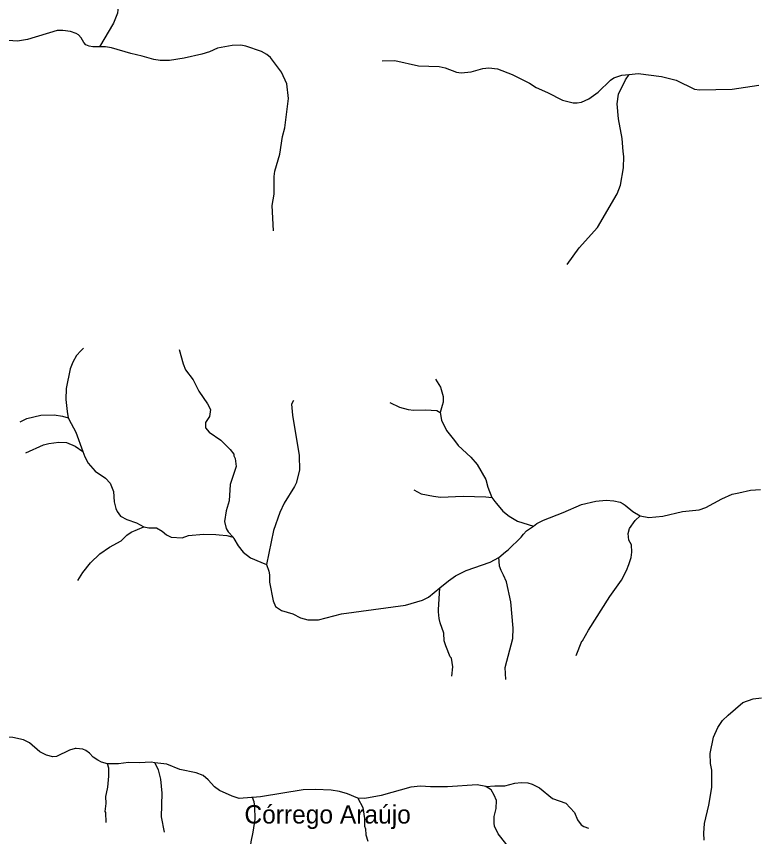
# Model space of a CAD drawing. Extents: x 396 to 422.2, y 7649.8 to 7677.6.
# Drawn here: x 418.881 to 422.13, y 7659.698 to 7663.274 of the extents above; entities that cross this region are included whole.
import ezdxf
from ezdxf.enums import TextEntityAlignment as Align

# ---------------------------------------------------------------- set-up
doc = ezdxf.new("R2010")
doc.units = 0
doc.header["$LTSCALE"] = 0.032
doc.layers.add('61', color=7, linetype='Continuous')
doc.layers.add('7', color=7, linetype='Continuous', lineweight=25)

msp = doc.modelspace()

# ---------------------------------------------------------------- linework, layer by layer
at = {"layer": '7'}
for points in [[(419.1658, 7663.6844), (419.1843, 7663.6415), (419.207, 7663.5626), (419.2258, 7663.5203), (419.2495, 7663.4776), (419.2741, 7663.4332), (419.309, 7663.3852), (419.3109, 7663.3808), (419.3181, 7663.3633), (419.3247, 7663.3476), (419.3247, 7663.3169), (419.3209, 7663.2878), (419.3047, 7663.244), (419.2429, 7663.1414)], [(419.2429, 7663.1414), (419.2223, 7663.1414), (419.2182, 7663.1414), (419.2135, 7663.1414), (419.1976, 7663.1438), (419.1839, 7663.1501), (419.1744, 7663.1594), (419.1626, 7663.1808), (419.1509, 7663.1941), (419.1416, 7663.1999), (419.1166, 7663.2075), (419.0825, 7663.2125), (419.0584, 7663.2124), (418.9289, 7663.1725), (418.8861, 7663.1662), (418.8265, 7663.1695), (418.6753, 7663.1853), (418.6446, 7663.1853), (418.6035, 7663.1807), (418.5732, 7663.1724), (418.5063, 7663.1394), (418.4717, 7663.1276), (418.4202, 7663.1209), (418.3705, 7663.1225)], [(420.0016, 7662.3393), (419.9963, 7662.4491), (420.0042, 7662.4995), (420.005, 7662.5757), (420.0076, 7662.5991), (420.0296, 7662.6726), (420.041, 7662.7503), (420.0504, 7662.7875), (420.0664, 7662.9155), (420.0601, 7662.9793), (420.0365, 7663.0313), (419.9884, 7663.0943), (419.9726, 7663.1077), (419.9487, 7663.1214), (419.8811, 7663.1447), (419.8591, 7663.1486), (419.8217, 7663.147), (419.7574, 7663.1348), (419.7229, 7663.1197), (419.6888, 7663.1088), (419.6119, 7663.0912), (419.5481, 7663.0816), (419.5079, 7663.0818), (419.4801, 7663.0858), (419.4297, 7663.1009), (419.3802, 7663.1116), (419.2951, 7663.1373), (419.2692, 7663.1414), (419.2429, 7663.1414)], [(420.4757, 7663.0807), (420.5311, 7663.0814), (420.6346, 7663.0585), (420.7243, 7663.056), (420.7498, 7663.0495), (420.7994, 7663.0308), (420.82, 7663.0285), (420.8643, 7663.0323), (420.9143, 7663.0464), (420.9402, 7663.0497), (420.9785, 7663.045), (421.0423, 7663.0212), (421.1185, 7662.9823), (421.1477, 7662.9644), (421.197, 7662.9423), (421.2614, 7662.9085), (421.308, 7662.8976), (421.3256, 7662.8967), (421.3444, 7662.8999), (421.3762, 7662.9139), (421.4172, 7662.9428), (421.4706, 7662.9961), (421.4859, 7663.0054), (421.5212, 7663.0178), (421.5531, 7663.0207)], [(421.2818, 7662.1927), (421.3344, 7662.2656), (421.4152, 7662.3538), (421.4997, 7662.4998), (421.5147, 7662.5377), (421.5274, 7662.6143), (421.5298, 7662.6626), (421.5259, 7662.6853), (421.5226, 7662.7419), (421.5068, 7662.8277), (421.5004, 7662.8925), (421.5068, 7662.9354), (421.5372, 7662.9968), (421.5531, 7663.0207)], [(421.5531, 7663.0207), (421.5924, 7663.0242), (421.694, 7663.0113), (421.7571, 7662.9955), (421.837, 7662.9573), (421.8589, 7662.9541), (422.0024, 7662.9572), (422.1175, 7662.9743)], [(419.1731, 7661.8275), (419.1621, 7661.8159), (419.143, 7661.796), (419.1261, 7661.7671), (419.1155, 7661.7374), (419.0975, 7661.6522), (419.0961, 7661.6044), (419.1021, 7661.5511), (419.1061, 7661.5244)], [(419.5906, 7661.8218), (419.6075, 7661.7598), (419.6181, 7661.7326), (419.6508, 7661.6898), (419.6758, 7661.6396), (419.7133, 7661.5849), (419.7264, 7661.5606), (419.7233, 7661.5304), (419.7045, 7661.503), (419.7046, 7661.4802), (419.7218, 7661.4607), (419.7724, 7661.4266), (419.8134, 7661.3865), (419.8287, 7661.3653), (419.8289, 7661.3586), (419.8351, 7661.3467), (419.8383, 7661.3121), (419.8129, 7661.2334), (419.8088, 7661.1617), (419.7954, 7661.1186), (419.7874, 7661.0727), (419.7956, 7661.0412), (419.8041, 7661.0273), (419.8256, 7661.0035)], [(420.7087, 7661.6929), (420.7292, 7661.6578), (420.739, 7661.6265), (420.7411, 7661.6171), (420.742, 7661.6035), (420.7411, 7661.5915), (420.7372, 7661.5772), (420.7291, 7661.5476)], [(420.0882, 7661.5988), (420.0804, 7661.5829), (420.0842, 7661.5356), (420.1136, 7661.3603), (420.1158, 7661.2961), (420.1006, 7661.2391), (420.0936, 7661.2239), (420.0486, 7661.1526), (420.03, 7661.1109), (420.0013, 7661.0329), (419.9711, 7660.8849)], [(420.5088, 7661.5907), (420.5507, 7661.5702), (420.5896, 7661.56), (420.6132, 7661.5569), (420.664, 7661.5593), (420.7141, 7661.5554), (420.7291, 7661.5476)], [(418.8974, 7661.5067), (418.9257, 7661.5204), (418.9875, 7661.5361), (419.0447, 7661.5369), (419.082, 7661.5314), (419.1061, 7661.5244)], [(420.7291, 7661.5476), (420.7346, 7661.514), (420.7564, 7661.4689), (420.7905, 7661.4245), (420.8065, 7661.4037), (420.8626, 7661.3517), (420.8892, 7661.3211), (420.9282, 7661.2545), (420.936, 7661.2212), (420.9541, 7661.1767)], [(419.1061, 7661.5244), (419.1187, 7661.4996), (419.1396, 7661.4614), (419.1704, 7661.3776)], [(418.9219, 7661.3709), (418.9991, 7661.406), (419.0221, 7661.4118), (419.0657, 7661.4172), (419.0992, 7661.4165), (419.1375, 7661.4001), (419.1704, 7661.3776)], [(419.1704, 7661.3776), (419.1793, 7661.3534), (419.1933, 7661.3258), (419.2245, 7661.2909), (419.2692, 7661.2607), (419.2895, 7661.2397), (419.3041, 7661.2024), (419.3073, 7661.1578), (419.3139, 7661.1287), (419.3199, 7661.1153), (419.3347, 7661.095), (419.3618, 7661.0814), (419.4045, 7661.0663), (419.4365, 7661.049), (419.4366, 7661.049)], [(420.6134, 7661.2107), (420.646, 7661.1924), (420.6989, 7661.1829), (420.7295, 7661.1774), (420.8285, 7661.182), (420.9281, 7661.1788), (420.9541, 7661.1767)], [(421.6004, 7661.0969), (421.6382, 7661.0891), (421.6997, 7661.0959), (421.7858, 7661.115), (421.8584, 7661.1232), (421.8876, 7661.1324), (421.9574, 7661.1705), (422.0024, 7661.1907), (422.0309, 7661.197), (422.0818, 7661.2082), (422.1258, 7661.2121)], [(420.9541, 7661.1767), (420.9672, 7661.1588), (420.9735, 7661.1501), (421.0017, 7661.1169), (421.0292, 7661.095), (421.0662, 7661.0737), (421.1349, 7661.0523)], [(421.1349, 7661.0523), (421.1498, 7661.0627), (421.1797, 7661.0783), (421.265, 7661.1113), (421.3444, 7661.1466), (421.407, 7661.1606), (421.4527, 7661.1644), (421.4851, 7661.1627), (421.5128, 7661.1566), (421.5268, 7661.1497), (421.5354, 7661.1429), (421.5693, 7661.116), (421.6004, 7661.0969)], [(421.3219, 7660.4879), (421.3455, 7660.5505), (421.3493, 7660.5521), (421.3748, 7660.5989), (421.4688, 7660.7444), (421.5195, 7660.8163), (421.5417, 7660.858), (421.551, 7660.8852), (421.561, 7660.9144), (421.5641, 7660.9384), (421.5626, 7660.9701), (421.5515, 7660.991), (421.5483, 7661.0198), (421.5546, 7661.0416), (421.5787, 7661.0759), (421.6004, 7661.0969)], [(419.1489, 7660.815), (419.1698, 7660.8498), (419.2033, 7660.8915), (419.245, 7660.9309), (419.2865, 7660.9603), (419.3378, 7660.9877), (419.3624, 7661.012), (419.3809, 7661.0259), (419.4366, 7661.049)], [(419.4366, 7661.049), (419.4574, 7661.0439), (419.4917, 7661.0439), (419.5157, 7661.0298), (419.5353, 7661.0141), (419.5561, 7661.0034), (419.6031, 7661.0003), (419.6313, 7661.0114), (419.6963, 7661.0162), (419.7507, 7661.0148), (419.7641, 7661.0145), (419.7985, 7661.0105), (419.8256, 7661.0035)], [(420.9841, 7660.9147), (421.0134, 7660.9393), (421.025, 7660.9484), (421.0822, 7661.0039), (421.0925, 7661.0165), (421.1046, 7661.0311), (421.1349, 7661.0523)], [(419.8256, 7661.0035), (419.8294, 7660.9972), (419.8483, 7660.9654), (419.87, 7660.9376), (419.9011, 7660.9133), (419.9465, 7660.8943), (419.9711, 7660.8849)], [(419.9711, 7660.8849), (419.9819, 7660.8552), (419.9843, 7660.8395), (419.9836, 7660.8069), (419.9996, 7660.7267), (420.0107, 7660.7014), (420.0363, 7660.6847), (420.0865, 7660.6695), (420.1188, 7660.6518), (420.1507, 7660.643), (420.1976, 7660.6438), (420.2977, 7660.67), (420.577, 7660.7073), (420.6509, 7660.7285), (420.6776, 7660.7428), (420.7268, 7660.7832)], [(420.7268, 7660.7832), (420.7643, 7660.814), (420.7947, 7660.8355), (420.8415, 7660.8577), (420.946, 7660.8952), (420.9841, 7660.9147)], [(421.0153, 7660.3833), (421.0124, 7660.4352), (421.0456, 7660.5624), (421.0473, 7660.6066), (421.0361, 7660.7218), (421.0171, 7660.8085), (421.0041, 7660.8378), (420.9947, 7660.8588), (420.9878, 7660.8775), (420.9851, 7660.8986), (420.9841, 7660.9147)], [(420.7799, 7660.3973), (420.7833, 7660.4379), (420.778, 7660.4762), (420.7727, 7660.4825), (420.7525, 7660.5293), (420.746, 7660.552), (420.7451, 7660.5855), (420.7281, 7660.6308), (420.724, 7660.6488), (420.7219, 7660.6782), (420.7213, 7660.6864), (420.7268, 7660.7832)], [(421.8799, 7659.6831), (421.8784, 7659.7135), (421.8816, 7659.7549), (421.8996, 7659.8348), (421.9134, 7659.9125), (421.9134, 7659.9873), (421.9078, 7660.0165), (421.9063, 7660.0612), (421.9201, 7660.1316), (421.9393, 7660.1747), (421.959, 7660.2038), (421.9838, 7660.2285), (422.0484, 7660.2837), (422.0934, 7660.2984), (422.1301, 7660.3039)], [(419.2779, 7660.0152), (419.252, 7660.0226), (419.2356, 7660.0309), (419.2154, 7660.0446), (419.1995, 7660.0615), (419.1832, 7660.0733), (419.17, 7660.079), (419.1417, 7660.083), (419.1368, 7660.0818), (419.1123, 7660.0758), (419.0559, 7660.0483), (419.0395, 7660.0466), (419.0115, 7660.053), (418.9824, 7660.068), (418.9375, 7660.1068), (418.9112, 7660.1204), (418.8646, 7660.1308), (418.7494, 7660.1389), (418.7216, 7660.1367), (418.6991, 7660.1291)], [(419.272, 7659.7593), (419.2706, 7659.8029), (419.2676, 7659.8077), (419.2721, 7659.8426), (419.2705, 7659.8733), (419.2784, 7659.9069), (419.2791, 7659.9133), (419.2842, 7659.9615), (419.2833, 7659.9969), (419.2779, 7660.0152)], [(419.4844, 7660.0207), (419.4688, 7660.0228), (419.4166, 7660.0203), (419.3691, 7660.0216), (419.3259, 7660.016), (419.2779, 7660.0152)], [(419.9096, 7659.8686), (419.9058, 7659.8683), (419.8524, 7659.8639), (419.8211, 7659.8747), (419.7665, 7659.8998), (419.7446, 7659.9153), (419.7161, 7659.9461), (419.6948, 7659.9642), (419.6642, 7659.9763), (419.5936, 7659.9916), (419.5362, 7660.0138), (419.4844, 7660.0207)], [(419.5271, 7659.7173), (419.5138, 7659.7845), (419.5161, 7659.8881), (419.51, 7659.9495), (419.5002, 7659.9889), (419.4844, 7660.0207)], [(420.9274, 7659.9174), (420.8892, 7659.9245), (420.761, 7659.9157), (420.6862, 7659.9157), (420.6431, 7659.9187), (420.6011, 7659.9133), (420.4716, 7659.8773), (420.4005, 7659.8638), (420.37, 7659.8656)], [(420.9274, 7659.9174), (420.9672, 7659.9195), (421.01, 7659.9195), (421.0541, 7659.9308), (421.0817, 7659.9347), (421.1111, 7659.9331), (421.1298, 7659.9274), (421.1619, 7659.9107), (421.2181, 7659.8638), (421.2766, 7659.8447), (421.3149, 7659.8029), (421.3277, 7659.7713), (421.3428, 7659.7504), (421.3553, 7659.7421), (421.3752, 7659.7354)], [(420.37, 7659.8656), (420.3244, 7659.8853), (420.2889, 7659.8955), (420.2534, 7659.9004), (420.1844, 7659.9044), (420.1306, 7659.9021), (419.9444, 7659.8714), (419.9096, 7659.8686)], [(421.0726, 7659.4967), (421.0725, 7659.4971), (421.05, 7659.5635), (421.0457, 7659.5671), (421.0314, 7659.6396), (421.0143, 7659.6678), (420.9816, 7659.7108), (420.9661, 7659.7433), (420.9637, 7659.7574), (420.9643, 7659.7858), (420.9725, 7659.8203), (420.974, 7659.8563), (420.9646, 7659.8786), (420.9502, 7659.9017), (420.9274, 7659.9174)], [(419.8979, 7659.5144), (419.8928, 7659.5763), (419.9038, 7659.6751), (419.9133, 7659.7175), (419.9213, 7659.7739), (419.9208, 7659.8301), (419.9181, 7659.85), (419.9096, 7659.8686)], [(420.37, 7659.8656), (420.3918, 7659.8247), (420.3982, 7659.7771), (420.3983, 7659.7446), (420.4031, 7659.7321), (420.4048, 7659.7067), (420.4125, 7659.6779)]]:
    msp.add_lwpolyline(points, dxfattribs=at)

# ---------------------------------------------------------------- texts
at = {"layer": '61'}
msp.add_text('Córrego Araújo', height=0.08, dxfattribs=at).set_placement((420.2377, 7659.7554), align=Align.CENTER)

doc.saveas('drawing.dxf')
